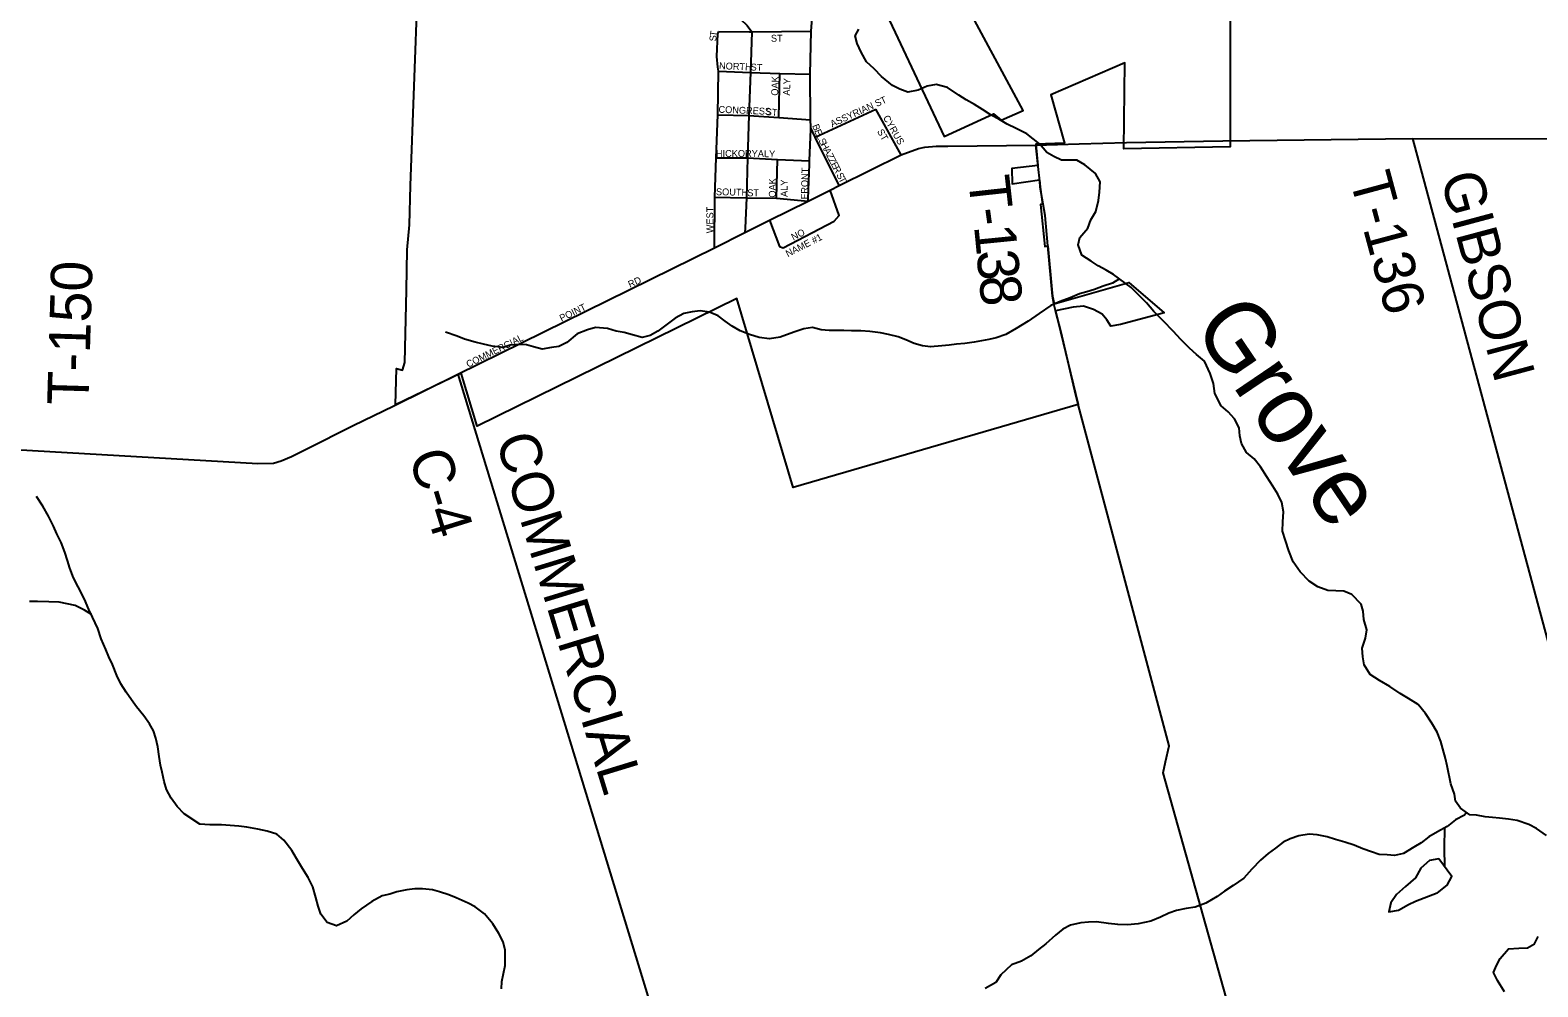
# Model space of a CAD drawing. Extents: x 1643459 to 2064572, y 425441 to 780708.
# Drawn here: x 1805814 to 1816774, y 638720 to 645672 of the extents above; entities that cross this region are included whole.
import ezdxf

# ---------------------------------------------------------------- set-up
doc = ezdxf.new("R2010")
doc.units = 0
for name, color, linetype in [('GM_X_Airport_Class_2', 7, 'Continuous'), ('GM_X_Airport_Class_3', 7, 'Continuous'), ('GM_X_Interchange_Ramps', 7, 'Continuous'), ('GM_X_Major_River', 7, 'Continuous'), ('GM_X_Major_River_Text', 7, 'Continuous'), ('GM_X_Minor_Lake', 7, 'Continuous'), ('GM_X_Rail_Line_Text', 7, 'Continuous'), ('GM_X_Section_Text', 7, 'Continuous'), ('GM_X_Township_Subdivision_Text', 7, 'Continuous'), ('GM_X_US_Route', 7, 'Continuous'), ('RD_X_Text', 7, 'Continuous')]:
    doc.layers.add(name, color=color, linetype=linetype)

msp = doc.modelspace()

# ---------------------------------------------------------------- linework, layer by layer
at = {"layer": 'GM_X_Airport_Class_2'}
for points in [[(1811488, 644969), (1811487, 645021), (1811484, 645351), (1811492, 645665), (1811505, 645851)], [(1810814, 645402), (1810806, 645480), (1810813, 645646), (1810820, 645663)], [(1810820, 645663), (1811044, 645661)], [(1811044, 645661), (1811061, 645661), (1811492, 645665)], [(1810788, 644091), (1810792, 644458), (1810801, 644743), (1810813, 645057), (1810817, 645373), (1810814, 645402)], [(1810817, 645373), (1811050, 645365), (1811263, 645358), (1811484, 645351)], [(1811256, 645037), (1811263, 645358)], [(1810813, 645057), (1811038, 645051), (1811038, 645051)], [(1811038, 645051), (1811256, 645037), (1811487, 645021)], [(1811521, 644895), (1811961, 645099)], [(1812147, 644766), (1811961, 645099)], [(1811480, 644724), (1811488, 644950), (1811488, 644962), (1811488, 644969)], [(1811695, 644542), (1811521, 644895), (1811488, 644962)], [(1810801, 644743), (1811028, 644743), (1811247, 644733), (1811480, 644722)], [(1811240, 644450), (1811247, 644733)], [(1811470, 644430), (1811470, 644446), (1811479, 644698), (1811480, 644722), (1811480, 644724)], [(1811188, 644290), (1811261, 644101), (1811289, 644089), (1811660, 644285), (1811694, 644324), (1811630, 644510)], [(1810792, 644458), (1811016, 644453)], [(1811016, 644453), (1811022, 644453), (1811240, 644450), (1811470, 644430)], [(1808924, 643171), (1810788, 644091), (1811010, 644202)], [(1813269, 643635), (1813259, 643673), (1813256, 643686)]]:
    msp.add_lwpolyline(points, dxfattribs=at)
at = {"layer": 'GM_X_Major_River_Text'}
for points in [[(1813141, 644680), (1813124, 644837)], [(1815864, 644884), (1817755, 637853), (1818229, 635847), (1818377, 635282)], [(1813153, 644575), (1813141, 644680)], [(1813185, 644367), (1813157, 644531), (1813153, 644575)], [(1813212, 644105), (1813192, 644326), (1813185, 644367)], [(1813256, 643686), (1813245, 643739), (1813212, 644105)], [(1813416, 643020), (1813308, 643478), (1813269, 643635)], [(1818229, 635847), (1816811, 635918), (1816733, 635919), (1816687, 635949), (1816552, 636132), (1816480, 636182), (1816390, 636203), (1815292, 635907), (1814727, 637864), (1814051, 640276), (1814067, 640356), (1814095, 640470), (1813432, 642951), (1813416, 643020)]]:
    msp.add_lwpolyline(points, dxfattribs=at)
at = {"layer": 'GM_X_Minor_Lake'}
for points in [[(1808458, 642943), (1808924, 643171)], [(1808924, 643171), (1810545, 637868), (1811427, 634806), (1812158, 631464), (1812752, 628632), (1813224, 626697), (1813662, 625244), (1814030, 623882), (1814494, 622253), (1814649, 621689), (1814740, 621390), (1814825, 621131), (1814842, 621096)], [(1799682, 642973), (1799682, 642973), (1801129, 642890), (1804498, 642688), (1805706, 642624), (1807468, 642522), (1807583, 642525), (1807639, 642541), (1807714, 642573), (1807820, 642626), (1808163, 642799), (1808458, 642943)]]:
    msp.add_lwpolyline(points, dxfattribs=at)
at = {"layer": 'GM_X_Rail_Line_Text'}
msp.add_lwpolyline([(1814538, 645856), (1814538, 644823), (1813764, 644810), (1813772, 645435), (1813235, 645201), (1813333, 644850), (1813126, 644844), (1813140, 644689), (1812950, 644666), (1812954, 644554), (1813151, 644585), (1813157, 644531), (1813173, 644407), (1813158, 644404), (1813190, 644100), (1813212, 644104), (1813240, 643788), (1813245, 643739), (1813257, 643684), (1813802, 643837), (1814059, 643617), (1813741, 643534), (1813670, 643521), (1813642, 643567), (1813608, 643607), (1813544, 643641), (1813471, 643665), (1813397, 643659), (1813269, 643633), (1813432, 642951), (1811360, 642348), (1810951, 643721), (1809064, 642794), (1808946, 643180), (1808470, 642949), (1808477, 643214), (1808520, 643201), (1808537, 643258), (1808549, 643783), (1808555, 644076), (1808572, 644257), (1808579, 644542), (1808685, 647432)], dxfattribs=at)
msp.add_lwpolyline([(1811942, 645996), (1812458, 644900), (1812818, 645065), (1812872, 645018), (1813033, 645087), (1812914, 645309), (1812461, 646151)], close=True, dxfattribs=at)
at = {"layer": 'GM_X_Township_Subdivision_Text'}
for points in [[(1816054, 639650), (1815986, 639637), (1815923, 639582), (1815884, 639512), (1815812, 639449), (1815747, 639390), (1815705, 639331), (1815692, 639265), (1815762, 639276), (1815833, 639319), (1815885, 639343), (1816042, 639402)], [(1816042, 639402), (1816045, 639403), (1816114, 639458), (1816149, 639522), (1816054, 639650)]]:
    msp.add_lwpolyline(points, dxfattribs=at)
at = {"layer": 'GM_X_US_Route'}
for points in [[(1814393, 643178), (1814350, 643266), (1814294, 643316), (1814243, 643361), (1814179, 643423), (1814124, 643484), (1814052, 643558), (1813983, 643627), (1813930, 643691), (1813817, 643802), (1813689, 643897), (1813636, 643927), (1813578, 643960), (1813528, 643992), (1813460, 644037), (1813433, 644113), (1813444, 644164), (1813502, 644232), (1813525, 644293), (1813561, 644355), (1813580, 644434), (1813587, 644494), (1813593, 644570), (1813558, 644630), (1813481, 644693), (1813423, 644727), (1813363, 644728), (1813311, 644728), (1813255, 644753), (1813205, 644783), (1813152, 644847), (1813060, 644918), (1812981, 644957), (1812917, 644989), (1812855, 645024), (1812799, 645054), (1812736, 645095), (1812678, 645131), (1812618, 645166), (1812565, 645200), (1812483, 645255), (1812401, 645276), (1812335, 645266), (1812269, 645235), (1812195, 645222), (1812135, 645244), (1812083, 645269), (1812003, 645335), (1811950, 645392), (1811894, 645442), (1811855, 645512), (1811826, 645576), (1811812, 645630), (1811837, 645680)], [(1813733, 643865), (1813681, 643833), (1813614, 643812), (1813552, 643788), (1813496, 643771), (1813442, 643755), (1813374, 643726), (1813301, 643701), (1813233, 643672), (1813148, 643613), (1813070, 643557), (1812981, 643504), (1812907, 643461), (1812837, 643436), (1812784, 643424), (1812730, 643415), (1812676, 643404), (1812608, 643396), (1812548, 643389), (1812494, 643383), (1812442, 643378), (1812360, 643371), (1812300, 643379), (1812240, 643396), (1812180, 643422), (1812124, 643443), (1812054, 643461), (1811996, 643472), (1811918, 643481), (1811852, 643487), (1811786, 643488), (1811730, 643490), (1811622, 643489), (1811564, 643494), (1811502, 643512), (1811438, 643501), (1811366, 643478), (1811266, 643441), (1811189, 643428), (1811113, 643438), (1811044, 643461), (1810976, 643487), (1810918, 643522), (1810866, 643556), (1810815, 643595), (1810753, 643623), (1810685, 643632), (1810627, 643626), (1810567, 643613), (1810504, 643580), (1810436, 643528), (1810377, 643485), (1810321, 643454), (1810263, 643438), (1810193, 643459), (1810131, 643476), (1810073, 643484), (1810011, 643505), (1809923, 643511), (1809865, 643494), (1809791, 643465), (1809716, 643402), (1809658, 643374), (1809604, 643365), (1809536, 643353), (1809474, 643370), (1809422, 643384), (1809370, 643387), (1809304, 643382), (1809252, 643366), (1809172, 643375), (1809110, 643389), (1809050, 643404), (1808972, 643427), (1808918, 643447), (1808834, 643478)], [(1816838, 639819), (1816764, 639871), (1816710, 639900), (1816625, 639928), (1816561, 639939), (1816495, 639946), (1816445, 639950), (1816391, 639955), (1816329, 639967), (1816279, 639970), (1816211, 640018), (1816176, 640070), (1816168, 640120), (1816143, 640196), (1816116, 640326), (1816103, 640380), (1816083, 640450), (1816068, 640502), (1816042, 640570), (1816003, 640637), (1815957, 640705), (1815904, 640771), (1815834, 640816), (1815773, 640852), (1815699, 640903), (1815623, 640945), (1815556, 640990), (1815512, 641060), (1815501, 641118), (1815497, 641180), (1815522, 641254), (1815531, 641313), (1815509, 641389), (1815504, 641449), (1815490, 641501), (1815423, 641570), (1815363, 641596), (1815247, 641599), (1815175, 641626), (1815112, 641667), (1815046, 641735), (1814995, 641809), (1814964, 641887), (1814940, 641963), (1814919, 642032), (1814920, 642099), (1814926, 642171), (1814913, 642239), (1814885, 642301), (1814848, 642359), (1814803, 642426), (1814757, 642498), (1814712, 642556), (1814656, 642603), (1814621, 642667), (1814609, 642723), (1814602, 642781), (1814570, 642847), (1814523, 642899), (1814473, 642942), (1814426, 643032), (1814416, 643104), (1814393, 643178)], [(1809241, 638706), (1809243, 638759), (1809266, 638875), (1809267, 638933), (1809267, 638987), (1809252, 639047), (1809222, 639107), (1809177, 639177), (1809118, 639249), (1809050, 639300), (1808998, 639328), (1808912, 639367), (1808857, 639388), (1808789, 639410), (1808739, 639425), (1808667, 639433), (1808611, 639432), (1808551, 639424), (1808479, 639409), (1808428, 639394), (1808372, 639380), (1808298, 639341), (1808221, 639286), (1808167, 639244), (1808116, 639197), (1808040, 639162), (1807974, 639186), (1807927, 639247), (1807907, 639307), (1807890, 639369), (1807869, 639447), (1807835, 639515), (1807794, 639579), (1807750, 639653), (1807717, 639710), (1807658, 639786), (1807608, 639830), (1807538, 639851), (1807470, 639866), (1807388, 639880), (1807330, 639887), (1807268, 639893), (1807204, 639898), (1807120, 639897), (1807048, 639902), (1806933, 639978), (1806883, 640031), (1806840, 640091), (1806806, 640153), (1806787, 640213), (1806774, 640279), (1806762, 640331), (1806751, 640393), (1806743, 640463), (1806728, 640527), (1806710, 640579), (1806681, 640631), (1806641, 640688), (1806588, 640754), (1806550, 640806), (1806511, 640860), (1806473, 640921), (1806444, 640983), (1806412, 641061), (1806387, 641117), (1806365, 641171), (1806330, 641249), (1806307, 641323), (1806268, 641407), (1806240, 641461), (1806209, 641538), (1806164, 641626), (1806130, 641692), (1806103, 641762), (1806085, 641818), (1806066, 641878), (1806040, 641948), (1806009, 642012), (1805983, 642068), (1805946, 642139), (1805905, 642213), (1805859, 642283)], [(1806259, 641425), (1806210, 641456), (1806140, 641490), (1806082, 641503), (1806024, 641515), (1805950, 641518), (1805868, 641519), (1805808, 641521)], [(1816255, 639987), (1816241, 639968), (1816176, 639933), (1816114, 639885), (1816044, 639846), (1815981, 639809), (1815925, 639767), (1815874, 639734), (1815798, 639689), (1815732, 639675), (1815680, 639678), (1815622, 639681), (1815566, 639701), (1815502, 639722), (1815440, 639748), (1815370, 639771), (1815303, 639791), (1815243, 639810), (1815169, 639824), (1815113, 639829), (1815037, 639818), (1814974, 639796), (1814922, 639771), (1814866, 639728), (1814815, 639688), (1814757, 639639), (1814696, 639574), (1814638, 639510), (1814559, 639455), (1814497, 639416), (1814442, 639377), (1814360, 639327), (1814283, 639298), (1814217, 639289), (1814147, 639274), (1814091, 639256), (1814031, 639227), (1813962, 639198), (1813868, 639178), (1813792, 639171), (1813720, 639172), (1813652, 639181), (1813566, 639193), (1813508, 639190), (1813452, 639184), (1813378, 639167), (1813321, 639138), (1813267, 639096), (1813198, 639033), (1813144, 638990), (1813089, 638944), (1813021, 638907), (1812949, 638880), (1812870, 638807), (1812833, 638751), (1812757, 638708)], [(1816097, 639591), (1816095, 639730), (1816099, 639876)], [(1816533, 638684), (1816482, 638765), (1816452, 638823), (1816473, 638874), (1816501, 638926), (1816562, 638997), (1816636, 639000), (1816698, 639002), (1816750, 639031), (1816777, 639085)]]:
    msp.add_lwpolyline(points, dxfattribs=at)
at = {"layer": 'RD_X_Text'}
for points in [[(1810706, 645990), (1810978, 645751), (1811027, 645706), (1811061, 645661), (1811050, 645365), (1811038, 645051), (1811028, 644743), (1811022, 644453), (1811011, 644232)], [(1811011, 644232), (1811010, 644202), (1811188, 644290), (1811470, 644430), (1811630, 644510), (1811695, 644542), (1812147, 644766), (1812271, 644811), (1812317, 644821), (1812400, 644828), (1812486, 644829)], [(1812486, 644829), (1813124, 644837)], [(1813124, 644837), (1813440, 644846)], [(1813440, 644846), (1813785, 644856), (1814485, 644867), (1815864, 644884), (1819363, 644883)]]:
    msp.add_lwpolyline(points, dxfattribs=at)

# ---------------------------------------------------------------- texts
at = {"layer": 'GM_X_Airport_Class_3'}
for s, rotation, p in [('S', 87.978, (1810802, 645590)), ('T', 81.0316, (1810804, 645623)), ('ST', 0, (1811199, 645588)), ('NORTH', 357.6154, (1810821, 645389)), ('ST', 356.4254, (1811050, 645380)), ('OAK', 88.0918, (1811251, 645195)), ('ALY', 88.0261, (1811337, 645196)), ('ASSYRIAN ST', 24.5494, (1811644, 644965)), ('CONGRESS', 357.6457, (1810817, 645072)), ('ST', 356.4262, (1811160, 645054)), ('CYRUS', 299.8971, (1812012, 645036)), ('B', 291.3549, (1811498, 644978)), ('E', 291.8901, (1811513, 644940)), ('L', 295.5325, (1811527, 644905)), ('ST', 299.7432, (1811969, 644936)), ('S', 297.3476, (1811543, 644871)), ('H', 297.4465, (1811560, 644840)), ('A', 297.4155, (1811580, 644801)), ('HICKORY', 0, (1810799, 644751)), ('ALY', 358.0264, (1811103, 644751)), ('Z', 297.4429, (1811600, 644762)), ('Z', 297.4593, (1811616, 644730)), ('E', 297.4327, (1811633, 644699)), ('OAK', 90, (1811234, 644455)), ('FRONT', 88.7553, (1811467, 644442)), ('R', 297.4124, (1811649, 644668)), ('S', 297.4202, (1811673, 644621)), ('T', 297.4198, (1811689, 644590)), ('SOUTH', 358.7554, (1810799, 644473)), ('ST', 0, (1811027, 644465)), ('ALY', 90, (1811320, 644460)), ('WEST', 90, (1810780, 644196)), ('NAME #1', 26.9956, (1811322, 644022)), ('NO', 26.5699, (1811362, 644142)), ('RD', 23.9591, (1810174, 643799)), ('POINT', 26.0538, (1809677, 643553)), ('COMMERCIAL', 26.565, (1808999, 643218))]:
    msp.add_text(s, height=50, rotation=rotation, dxfattribs=at).set_placement(p)
at = {"layer": 'GM_X_Interchange_Ramps'}
msp.add_text('Grove', height=500, rotation=304.1156, dxfattribs=at).set_placement((1814258, 643522))
at = {"layer": 'GM_X_Major_River'}
for s, rotation, p in [('T', 276.2739, (1812632, 644600)), ('T-136', 285.0572, (1815404, 644597)), ('GIBSON', 284.9795, (1816065, 644604)), ('-', 277.8779, (1812658, 644368)), ('1', 275.692, (1812675, 644249)), ('3', 275.1327, (1812693, 644066)), ('T-150', 88.3151, (1806237, 642944)), ('8', 276.0528, (1812710, 643877))]:
    msp.add_text(s, height=300, rotation=rotation, dxfattribs=at).set_placement(p)
at = {"layer": 'GM_X_Section_Text'}
for s, rotation, p in [('COMMERCIAL', 286.9909, (1809196, 642699)), ('C-4', 287.2713, (1808563, 642580))]:
    msp.add_text(s, height=300, rotation=rotation, dxfattribs=at).set_placement(p)

doc.saveas('drawing.dxf')
